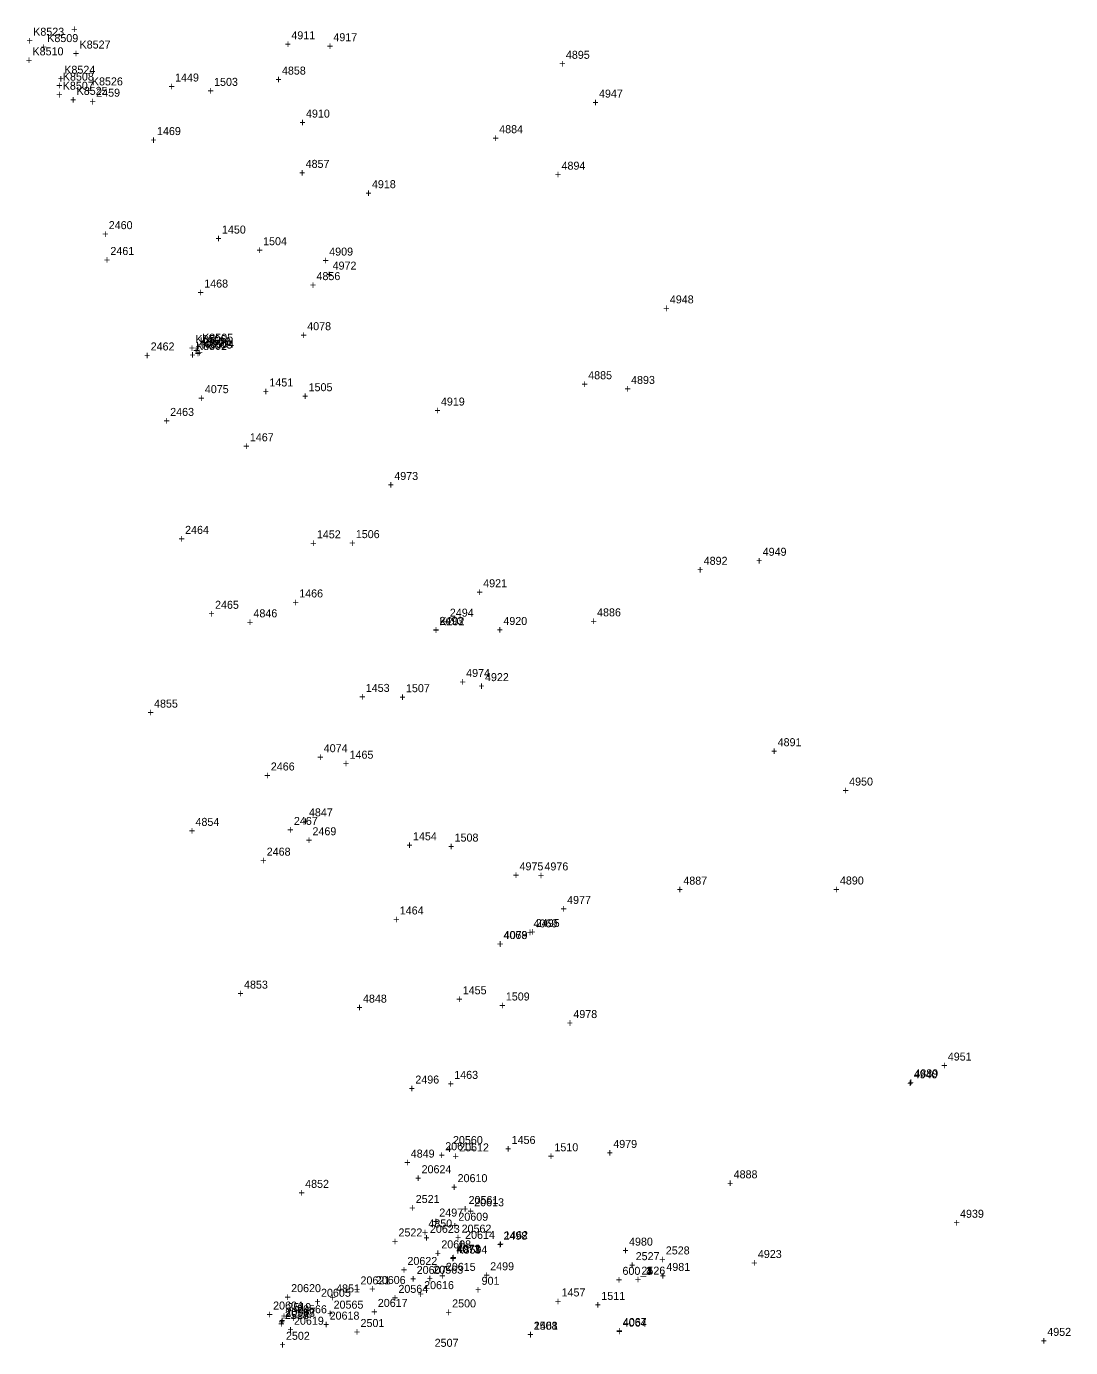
# Model space of a CAD drawing. Extents: x 1036751 to 1042192, y 772604 to 785439.
# Drawn here: x 1038428.6 to 1038754.4, y 778579.4 to 778992 of the extents above; entities that cross this region are included whole.
import ezdxf

# ---------------------------------------------------------------- set-up
doc = ezdxf.new("R2010")
doc.units = 0
for name, color, linetype in [('S_Control_Temp_Traverse', 7, 'Continuous'), ('S_Drainage_CB', 7, 'Continuous'), ('S_Drainage_Culvert_Top', 7, 'Continuous'), ('S_Drainage_Ditch_Line', 7, 'Continuous'), ('S_Drainage_Invert', 7, 'Continuous'), ('S_Drainage_Sump', 7, 'Continuous'), ('S_Ground_Elevation', 7, 'Continuous'), ('S_Ground_LevelString', 7, 'Continuous'), ('S_Property_IronPipeFound', 7, 'Continuous'), ('S_Property_Mailbox', 7, 'Continuous'), ('S_Roadway_Centerline', 7, 'Continuous'), ('S_Roadway_Edge_Pavement', 7, 'Continuous'), ('S_Roadway_Edge_Shoulder', 7, 'Continuous'), ('S_Traffic_Sign_SinglePost', 7, 'Continuous'), ('S_Trees_Bush', 7, 'Continuous'), ('S_Trees_Conifer_Pay', 7, 'Continuous'), ('S_Trees_Decid_Pay', 7, 'Continuous'), ('S_Utilities_GuyWire3', 7, 'Continuous'), ('S_Utilities_Hydrant', 7, 'Continuous'), ('S_Utilities_Pole_Power', 7, 'Continuous'), ('S_Utilities_Pole_Support3', 7, 'Continuous'), ('S_Utilities_UG_Water_Gate', 7, 'Continuous'), ('S_Utilities_UG_Water_Line', 7, 'Continuous')]:
    doc.layers.add(name, color=color, linetype=linetype)

msp = doc.modelspace()

# ---------------------------------------------------------------- texts
at = {"layer": 'S_Control_Temp_Traverse'}
for s, p in [('+', (1038555.37, 778802.21)), ('K202', (1038557.43, 778804.96)), ('901', (1038570.59, 778599.02)), ('901', (1038570.59, 778599.02)), ('901', (1038570.59, 778599.02)), ('901', (1038570.59, 778599.02)), ('901', (1038570.59, 778599.02)), ('600', (1038614.56, 778602.13)), ('600', (1038614.56, 778602.13)), ('600_4', (1038614.56, 778602.13)), ('600_2', (1038614.56, 778602.13)), ('600_3', (1038614.56, 778602.13)), ('600_1', (1038614.56, 778602.13)), ('+', (1038568.53, 778596.27)), ('+', (1038568.53, 778596.27)), ('+', (1038568.53, 778596.27)), ('+', (1038568.53, 778596.27)), ('+', (1038568.53, 778596.27)), ('+', (1038612.5, 778599.38)), ('+', (1038612.5, 778599.38)), ('+', (1038612.5, 778599.38)), ('+', (1038612.5, 778599.38)), ('+', (1038612.5, 778599.38)), ('+', (1038612.5, 778599.38))]:
    msp.add_text(s, height=2.5, dxfattribs=at).set_placement(p)
at = {"layer": 'S_Drainage_CB'}
for s, p in [('K8500', (1038482.66, 778892.29)), ('+', (1038480.6, 778889.54))]:
    msp.add_text(s, height=2.5, dxfattribs=at).set_placement(p)
at = {"layer": 'S_Drainage_Culvert_Top'}
for s, p in [('2517', (1038509.21, 778588.35)), ('+', (1038507.15, 778585.6))]:
    msp.add_text(s, height=2.5, dxfattribs=at).set_placement(p)
at = {"layer": 'S_Drainage_Ditch_Line'}
for s, p in [('20560', (1038561.66, 778642.96)), ('+', (1038559.59, 778640.21)), ('20561', (1038566.54, 778624.24)), ('+', (1038564.48, 778621.49)), ('+', (1038562.29, 778612.55)), ('20562', (1038564.35, 778615.3)), ('+', (1038553.47, 778599.74)), ('20563', (1038555.53, 778602.49)), ('20564', (1038544.64, 778596.49)), ('20565', (1038524.41, 778591.57)), ('+', (1038542.58, 778593.74)), ('20568', (1038509.29, 778588.98)), ('20567', (1038509.43, 778589.4)), ('+', (1038510.96, 778587.38)), ('20566', (1038513.02, 778590.13)), ('+', (1038522.35, 778588.82)), ('+', (1038507.22, 778586.23)), ('+', (1038507.37, 778586.65))]:
    msp.add_text(s, height=2.5, dxfattribs=at).set_placement(p)
at = {"layer": 'S_Drainage_Invert'}
for s, p in [('2518', (1038509.21, 778588.33)), ('+', (1038507.15, 778585.58))]:
    msp.add_text(s, height=2.5, dxfattribs=at).set_placement(p)
at = {"layer": 'S_Drainage_Sump'}
for s, p in [('K8501', (1038482.62, 778892.38)), ('+', (1038480.56, 778889.63))]:
    msp.add_text(s, height=2.5, dxfattribs=at).set_placement(p)
at = {"layer": 'S_Ground_Elevation'}
for s, p in [('K8523', (1038430.67, 778989.06)), ('4911', (1038511.23, 778987.95)), ('4917', (1038524.34, 778987.35)), ('+', (1038428.61, 778986.31)), ('K8527', (1038445.13, 778985.06)), ('+', (1038509.17, 778985.2)), ('+', (1038522.28, 778984.6)), ('+', (1038443.07, 778982.31)), ('+', (1038594.84, 778979.11)), ('4895', (1038596.9, 778981.86)), ('K8524', (1038440.37, 778977.19)), ('4858', (1038508.29, 778976.93)), ('+', (1038438.31, 778974.44)), ('K8525', (1038444.21, 778970.6)), ('+', (1038446.92, 778970.8)), ('K8526', (1038448.98, 778973.55)), ('+', (1038506.23, 778974.18)), ('+', (1038442.15, 778967.85)), ('+', (1038605.17, 778966.99)), ('4947', (1038607.23, 778969.74)), ('4910', (1038515.79, 778963.5)), ('+', (1038513.73, 778960.75)), ('4884', (1038576.09, 778958.63)), ('+', (1038574.03, 778955.88)), ('4857', (1038515.68, 778947.8)), ('4894', (1038595.54, 778947.23)), ('+', (1038513.62, 778945.05)), ('4918', (1038536.37, 778941.46)), ('+', (1038593.48, 778944.48)), ('+', (1038534.31, 778938.71)), ('+', (1038520.98, 778917.66)), ('4909', (1038523.04, 778920.41)), ('4856', (1038519.07, 778912.75)), ('+', (1038522.04, 778913.28)), ('4972', (1038524.1, 778916.03)), ('+', (1038517.01, 778910)), ('4948', (1038629.34, 778905.48)), ('+', (1038627.28, 778902.73)), ('K8506', (1038481.28, 778893.07)), ('K8505', (1038483.38, 778893.53)), ('+', (1038479.22, 778890.32)), ('+', (1038481.11, 778888.64)), ('+', (1038481.31, 778890.78)), ('K8502', (1038481.46, 778890.93)), ('+', (1038481.61, 778888.89)), ('K8503', (1038483.17, 778891.39)), ('K8504', (1038483.67, 778891.64)), ('+', (1038479.4, 778888.18)), ('4885', (1038603.86, 778881.8)), ('4893', (1038617.24, 778880.33)), ('+', (1038601.8, 778879.05)), ('+', (1038615.18, 778877.58)), ('4919', (1038557.9, 778873.58)), ('+', (1038555.84, 778870.83)), ('+', (1038541.28, 778847.59)), ('4973', (1038543.34, 778850.34)), ('4949', (1038658.31, 778826.67)), ('4892', (1038639.9, 778823.85)), ('+', (1038656.25, 778823.92)), ('+', (1038637.84, 778821.1)), ('+', (1038569.03, 778814.09)), ('4921', (1038571.1, 778816.84)), ('4846', (1038499.4, 778807.45)), ('4886', (1038606.63, 778807.75)), ('+', (1038497.34, 778804.7)), ('+', (1038575.32, 778802.32)), ('4920', (1038577.39, 778805.07)), ('+', (1038604.56, 778805)), ('4974', (1038565.78, 778788.82)), ('+', (1038563.72, 778786.07)), ('4922', (1038571.65, 778787.52)), ('+', (1038569.59, 778784.77)), ('4855', (1038468.38, 778779.25)), ('+', (1038466.32, 778776.5)), ('4891', (1038662.98, 778767.2)), ('+', (1038660.91, 778764.45)), ('+', (1038683.23, 778752.17)), ('4950', (1038685.29, 778754.92)), ('4847', (1038516.72, 778745.29)), ('4854', (1038481.31, 778742.32)), ('+', (1038514.66, 778742.54)), ('+', (1038479.25, 778739.57)), ('4975', (1038582.43, 778728.45)), ('4976', (1038590.21, 778728.41)), ('+', (1038580.37, 778725.7)), ('+', (1038588.15, 778725.66)), ('4887', (1038633.55, 778723.98)), ('4890', (1038682.41, 778724.02)), ('+', (1038631.49, 778721.23)), ('+', (1038680.35, 778721.27)), ('+', (1038595.22, 778715.19)), ('4977', (1038597.28, 778717.94)), ('4853', (1038496.46, 778691.5)), ('+', (1038494.4, 778688.75)), ('4848', (1038533.58, 778687.13)), ('+', (1038531.52, 778684.38)), ('4978', (1038599.23, 778682.31)), ('+', (1038597.17, 778679.56)), ('+', (1038714.02, 778666.29)), ('4951', (1038716.08, 778669.04)), ('4940', (1038705.43, 778663.49)), ('4889', (1038705.63, 778663.8)), ('+', (1038703.37, 778660.74)), ('+', (1038703.57, 778661.05)), ('20611', (1038559.25, 778641.04)), ('20612', (1038563.58, 778640.68)), ('4979', (1038611.68, 778641.75)), ('4849', (1038548.49, 778638.74)), ('+', (1038557.19, 778638.29)), ('+', (1038561.52, 778637.93)), ('+', (1038609.62, 778639)), ('+', (1038546.42, 778635.99)), ('20624', (1038551.87, 778633.85)), ('4888', (1038649.25, 778632.26)), ('4852', (1038515.53, 778629.29)), ('+', (1038549.81, 778631.1)), ('+', (1038561.05, 778628.32)), ('20610', (1038563.11, 778631.07)), ('+', (1038647.19, 778629.51)), ('+', (1038513.47, 778626.54)), ('+', (1038566.21, 778620.79)), ('20613', (1038568.28, 778623.54)), ('4939', (1038719.9, 778619.95)), ('4850', (1038553.99, 778616.92)), ('+', (1038561.28, 778616.27)), ('20609', (1038563.35, 778619.02)), ('+', (1038717.84, 778617.2)), ('+', (1038551.93, 778614.17)), ('+', (1038552.41, 778612.49)), ('20623', (1038554.47, 778615.24)), ('20614', (1038565.45, 778613.35)), ('20608', (1038558.02, 778610.39)), ('+', (1038563.39, 778610.6)), ('+', (1038614.54, 778608.5)), ('4980', (1038616.6, 778611.25)), ('4923', (1038656.81, 778607.39)), ('20622', (1038547.45, 778605.21)), ('+', (1038555.96, 778607.64)), ('20615', (1038559.44, 778603.37)), ('4981', (1038628.25, 778603.35)), ('+', (1038654.75, 778604.64)), ('20621', (1038532.8, 778599.14)), ('20606', (1038537.59, 778599.27)), ('+', (1038545.39, 778602.46)), ('+', (1038548.27, 778599.65)), ('20607', (1038550.34, 778602.4)), ('+', (1038557.38, 778600.62)), ('+', (1038626.19, 778600.6)), ('20620', (1038511.16, 778596.72)), ('20605', (1038520.48, 778595.28)), ('4851', (1038525.2, 778596.64)), ('+', (1038530.74, 778596.39)), ('+', (1038535.52, 778596.52)), ('20616', (1038552.66, 778597.66)), ('20604', (1038505.53, 778591.29)), ('+', (1038509.1, 778593.97)), ('+', (1038518.42, 778592.53)), ('+', (1038523.14, 778593.89)), ('20617', (1038538.2, 778592.11)), ('+', (1038550.6, 778594.91)), ('+', (1038503.47, 778588.54)), ('20618', (1038523.17, 778588.14)), ('+', (1038536.14, 778589.36)), ('+', (1038509.98, 778583.79)), ('20619', (1038512.05, 778586.54)), ('+', (1038521.11, 778585.39)), ('4952', (1038747.12, 778583.07)), ('+', (1038745.06, 778580.32))]:
    msp.add_text(s, height=2.5, dxfattribs=at).set_placement(p)
at = {"layer": 'S_Ground_LevelString'}
for s, p in [('1462', (1038577.64, 778613.28)), ('+', (1038575.58, 778610.53)), ('1461', (1038586.96, 778585.02)), ('+', (1038584.89, 778582.27))]:
    msp.add_text(s, height=2.5, dxfattribs=at).set_placement(p)
at = {"layer": 'S_Property_IronPipeFound'}
for s, p in [('2462', (1038467.32, 778890.79)), ('+', (1038465.26, 778888.04)), ('2521', (1038550.04, 778624.56)), ('+', (1038547.98, 778621.81))]:
    msp.add_text(s, height=2.5, dxfattribs=at).set_placement(p)
at = {"layer": 'S_Property_Mailbox'}
for s, p in [('+', (1038448.27, 778967.27)), ('2459', (1038450.33, 778970.02))]:
    msp.add_text(s, height=2.5, dxfattribs=at).set_placement(p)
at = {"layer": 'S_Roadway_Centerline'}
for s, p in [('1449', (1038474.94, 778974.77)), ('+', (1038472.87, 778972.02)), ('1450', (1038489.57, 778927.28)), ('+', (1038487.51, 778924.53)), ('+', (1038502.3, 778876.79)), ('1451', (1038504.37, 778879.54)), ('1452', (1038519.19, 778832.12)), ('+', (1038517.13, 778829.37)), ('+', (1038532.39, 778781.41)), ('1453', (1038534.45, 778784.16)), ('1454', (1038549.18, 778737.82)), ('+', (1038547.11, 778735.07)), ('+', (1038562.64, 778686.99)), ('1455', (1038564.71, 778689.74)), ('1456', (1038579.98, 778643)), ('+', (1038577.92, 778640.25)), ('1457', (1038595.55, 778595.39)), ('+', (1038593.49, 778592.64)), ('2508', (1038586.86, 778584.99)), ('2507', (1038555.95, 778579.65)), ('+', (1038584.8, 778582.24))]:
    msp.add_text(s, height=2.5, dxfattribs=at).set_placement(p)
at = {"layer": 'S_Roadway_Edge_Pavement'}
for s, p in [('1503', (1038487.11, 778973.41)), ('+', (1038485.05, 778970.66)), ('1469', (1038469.3, 778958.04)), ('+', (1038467.24, 778955.29)), ('1504', (1038502.41, 778923.64)), ('+', (1038500.35, 778920.89)), ('1468', (1038484.04, 778910.42)), ('+', (1038481.98, 778907.67)), ('1505', (1038516.61, 778878.06)), ('+', (1038514.55, 778875.31)), ('+', (1038496.21, 778859.67)), ('1467', (1038498.27, 778862.42)), ('1506', (1038531.34, 778832.18)), ('+', (1038529.28, 778829.43)), ('1466', (1038513.68, 778813.66)), ('+', (1038511.62, 778810.91)), ('+', (1038544.93, 778781.32)), ('1507', (1038546.99, 778784.07)), ('+', (1038527.33, 778760.55)), ('1465', (1038529.39, 778763.3)), ('1508', (1038562.17, 778737.42)), ('+', (1038560.11, 778734.67)), ('1464', (1038545.06, 778714.66)), ('+', (1038543, 778711.91)), ('1509', (1038578.16, 778687.8)), ('+', (1038576.1, 778685.05)), ('1463', (1038562.06, 778663.32)), ('+', (1038560, 778660.57)), ('1510', (1038593.32, 778640.71)), ('+', (1038591.26, 778637.96)), ('2498', (1038577.42, 778613.09)), ('+', (1038575.36, 778610.34)), ('2499', (1038573.28, 778603.55)), ('+', (1038571.22, 778600.8)), ('2500', (1038561.41, 778591.96)), ('+', (1038605.9, 778591.55)), ('1511', (1038607.96, 778594.3)), ('+', (1038559.35, 778589.21)), ('+', (1038530.75, 778583.08)), ('2501', (1038532.81, 778585.83)), ('+', (1038507.48, 778579.09)), ('2502', (1038509.54, 778581.84))]:
    msp.add_text(s, height=2.5, dxfattribs=at).set_placement(p)
at = {"layer": 'S_Roadway_Edge_Shoulder'}
msp.add_text('+', height=2.5, dxfattribs=at).set_placement((1038442.55, 778989.87))
at = {"layer": 'S_Traffic_Sign_SinglePost'}
for s, p in [('2496', (1038549.92, 778661.86)), ('+', (1038547.85, 778659.11)), ('2497', (1038557.39, 778620.33)), ('+', (1038555.33, 778617.58)), ('+', (1038618.41, 778599.43)), ('2526', (1038620.47, 778602.18)), ('2519', (1038509.99, 778590.8)), ('+', (1038507.93, 778588.05))]:
    msp.add_text(s, height=2.5, dxfattribs=at).set_placement(p)
at = {"layer": 'S_Trees_Bush'}
for s, p in [('K8509', (1038435.05, 778987.08)), ('K8510', (1038430.45, 778982.94)), ('+', (1038432.99, 778984.33)), ('+', (1038428.39, 778980.19))]:
    msp.add_text(s, height=2.5, dxfattribs=at).set_placement(p)
at = {"layer": 'S_Trees_Conifer_Pay'}
for s, p in [('+', (1038452.18, 778925.92)), ('2460', (1038454.24, 778928.67)), ('+', (1038452.7, 778917.85)), ('2461', (1038454.76, 778920.6)), ('2463', (1038473.42, 778870.34)), ('+', (1038471.35, 778867.59)), ('+', (1038476.01, 778830.76)), ('2464', (1038478.07, 778833.51)), ('2465', (1038487.41, 778810.11)), ('+', (1038485.35, 778807.36)), ('+', (1038502.76, 778756.87)), ('2466', (1038504.82, 778759.62)), ('2522', (1038544.66, 778614.12)), ('+', (1038542.6, 778611.37))]:
    msp.add_text(s, height=2.5, dxfattribs=at).set_placement(p)
at = {"layer": 'S_Trees_Decid_Pay'}
for s, p in [('K8508', (1038439.92, 778975.05)), ('+', (1038437.86, 778972.3)), ('K8507', (1038439.88, 778972.2)), ('+', (1038437.82, 778969.45))]:
    msp.add_text(s, height=2.5, dxfattribs=at).set_placement(p)
at = {"layer": 'S_Utilities_GuyWire3'}
for s, p in [('2494', (1038560.69, 778807.65)), ('+', (1038558.63, 778804.9)), ('2469', (1038517.82, 778739.39)), ('+', (1038515.76, 778736.64)), ('2468', (1038503.54, 778733.02)), ('+', (1038501.48, 778730.27)), ('2528', (1038628.08, 778608.5)), ('+', (1038626.02, 778605.75))]:
    msp.add_text(s, height=2.5, dxfattribs=at).set_placement(p)
at = {"layer": 'S_Utilities_Hydrant'}
for s, p in [('2495', (1038587.51, 778710.74)), ('+', (1038585.45, 778707.99))]:
    msp.add_text(s, height=2.5, dxfattribs=at).set_placement(p)
at = {"layer": 'S_Utilities_Pole_Power'}
for s, p in [('+', (1038555.38, 778802.33)), ('2493', (1038557.44, 778805.08)), ('+', (1038616.62, 778603.96)), ('2527', (1038618.68, 778606.71))]:
    msp.add_text(s, height=2.5, dxfattribs=at).set_placement(p)
at = {"layer": 'S_Utilities_Pole_Support3'}
for s, p in [('+', (1038509.96, 778739.86)), ('2467', (1038512.02, 778742.61))]:
    msp.add_text(s, height=2.5, dxfattribs=at).set_placement(p)
at = {"layer": 'S_Utilities_UG_Water_Gate'}
for s, p in [('4072', (1038562.83, 778609.06)), ('K8594', (1038562.72, 778608.76)), ('+', (1038560.65, 778606.01)), ('+', (1038560.77, 778606.31))]:
    msp.add_text(s, height=2.5, dxfattribs=at).set_placement(p)
at = {"layer": 'S_Utilities_UG_Water_Line'}
for s, p in [('4078', (1038516.18, 778897.11)), ('+', (1038514.12, 778894.36)), ('4075', (1038484.23, 778877.45)), ('+', (1038482.17, 778874.7)), ('4074', (1038521.33, 778765.32)), ('+', (1038519.27, 778762.57)), ('4069', (1038586.8, 778710.62)), ('4068', (1038577.41, 778706.99)), ('4079', (1038577.52, 778706.98)), ('+', (1038584.74, 778707.87)), ('+', (1038575.35, 778704.24)), ('+', (1038575.46, 778704.23)), ('4073', (1038562.7, 778608.94)), ('4071', (1038562.86, 778608.88)), ('+', (1038560.64, 778606.19)), ('+', (1038560.8, 778606.13)), ('+', (1038612.57, 778583.18)), ('+', (1038612.62, 778583.41)), ('4064', (1038614.63, 778585.93)), ('4067', (1038614.68, 778586.16))]:
    msp.add_text(s, height=2.5, dxfattribs=at).set_placement(p)

doc.saveas('drawing.dxf')
